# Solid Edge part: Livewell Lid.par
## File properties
Author: m_hel
Template: Iso Metric Part.par
Last saved by: m_hel
Revision: 15
Application: Solid Edge
Accuracy: 0,990
Username: m_hel
Material: Textured White
Face Style: White painted
Fill Style: ANSI36(Marble)
Virtual Style: ANSI36(Marble)
Grouping: Uncategorized
LibraryName: Custom Materials
Coef. of Thermal Exp: 0.0
Thermal Conductivity: 0.0
Specific Heat: 0.0
Modulus of Elasticity: 0.0
Poisson's Ratio: 0.0
Yield Stress: 0.0
Ultimate Stress: 0.0
Elongation: 0.0
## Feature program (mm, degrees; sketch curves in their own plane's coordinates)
sketch for "unnamed Protrusion 1" plane through (0, 0, 0) normal (0, 0, 1) x-axis (1, 0, 0)
  line (-250, -175) -> (250, -175)
  line (250, -175) -> (250, 175)
  line (250, 175) -> (-250, 175)
  line (-250, 175) -> (-250, -175)
extrude "unnamed Protrusion 1" add finite 50 along -normal
fillet "Round_1" radius 20
fillet "Round_2" radius 20
thinwall "Thinwall_1"  Thickness = 10 mm
sketch for "unnamed Cutout 1" plane through (0, 0, 0) normal (0, 0, 1) x-axis (1, 0, 0)
  circle centre (0, -75) radius 35
extrude "unnamed Cutout 1" cut through along -normal
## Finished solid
Body 1: solid body, 36 faces, 74 edges, 40 vertices.
  Faces by surface: cylinder 17, plane 11, sphere 8
  Edges by curve: line 40, circle 34
Bounding box of the edges (mm; curved faces can reach further): 500.000 x 350.000 x 50.000, from (-250, -175, -50) to (250, 175, 0).
Cylindrical faces by radius (mm): R10 x8, R20 x8, R35 x1
Spherical faces by radius (mm): R10 x4, R20 x4
Planar faces by outward normal: +x 2, +y 2, +z 1, -x 2, -y 2, -z 2
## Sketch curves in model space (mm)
circle centre (0, -75, 0) radius 35
line (250, -175, 0) -> (250, 175, 0)
line (250, 175, 0) -> (-250, 175, 0)
line (-250, 175, 0) -> (-250, -175, 0)
line (-250, -175, 0) -> (250, -175, 0)
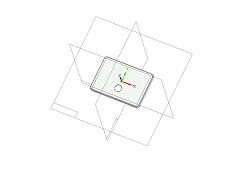
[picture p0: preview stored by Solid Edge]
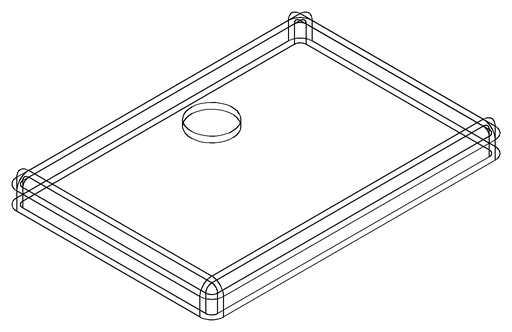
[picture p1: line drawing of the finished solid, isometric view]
